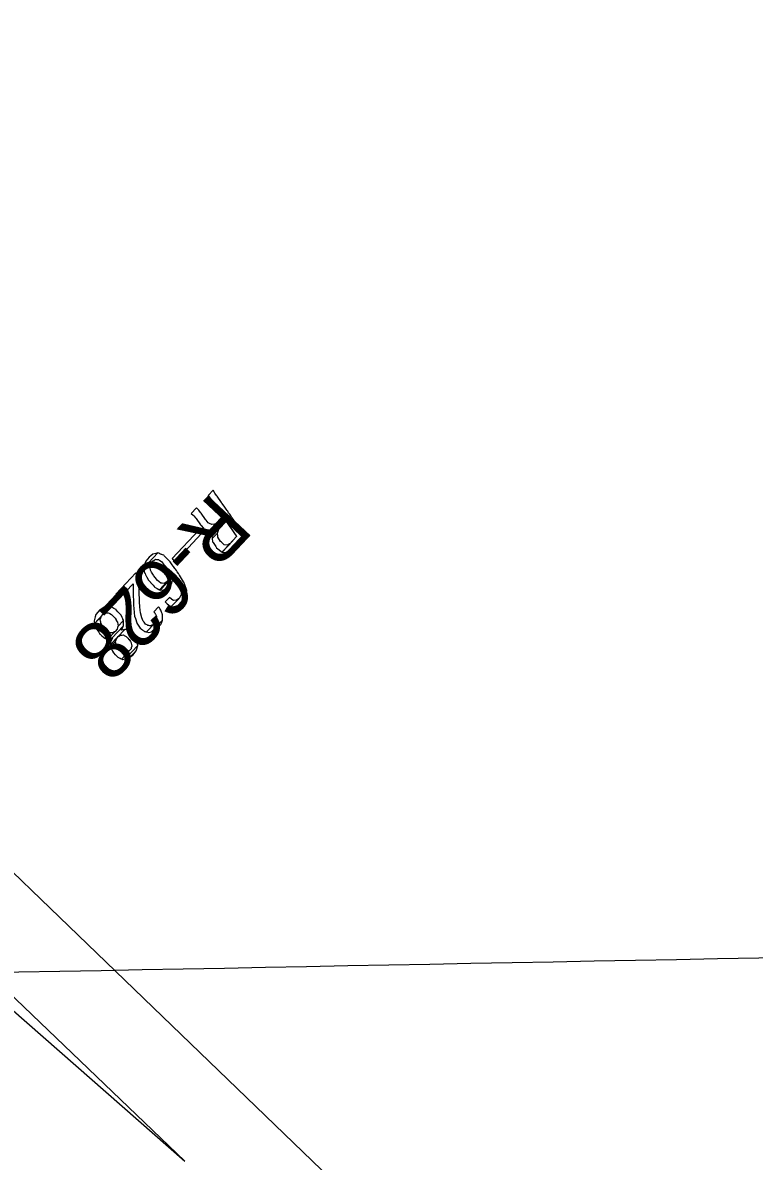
# Model space of a CAD drawing. Extents: x 3962991 to 3983549, y 181631 to 204078.
# Drawn here: x 3980223 to 3980744, y 188382 to 189193 of the extents above; entities that cross this region are included whole.
import ezdxf

# ---------------------------------------------------------------- set-up
doc = ezdxf.new("R2010")
doc.units = 0
for name, color, linetype in [('V-ANNO-MASK', 7, 'Continuous'), ('V-ANNO-MASK2', 7, 'Continuous'), ('V-GRID-MAJR', 7, 'Continuous'), ('V-RIVR-RANG-IDEN', 7, 'Continuous'), ('V-RRAP-FSHR', 7, 'Continuous'), ('V-TOPO-DPTH', 7, 'Continuous'), ('V-TOPO-MINR', 7, 'Continuous')]:
    doc.layers.add(name, color=color, linetype=linetype)

msp = doc.modelspace()

# ---------------------------------------------------------------- linework, layer by layer
at = {"layer": 'V-ANNO-MASK2'}
for points in [[(3980359.8, 188858.11), (3980358.66, 188859.76), (3980355.14, 188856.01), (3980356.29, 188854.37), (3980356.53, 188854.02), (3980357.7, 188852.34), (3980358.05, 188851.83), (3980361.14, 188847.41), (3980361.53, 188846.84), (3980362.97, 188844.78), (3980363.57, 188843.93), (3980364.51, 188842.56), (3980365.19, 188841.58), (3980365.41, 188841.28), (3980365.59, 188841.01), (3980355.97, 188830.74), (3980357.6, 188830.8), (3980360.25, 188832.18), (3980359.04, 188830.38), (3980357.87, 188827.31), (3980357.92, 188826.94), (3980367.94, 188837.63), (3980368.06, 188837.48), (3980368.67, 188836.6), (3980369.67, 188835.16), (3980370, 188834.69), (3980372.01, 188831.81), (3980372.54, 188831.04), (3980374.04, 188828.9), (3980375.14, 188827.33), (3980375.36, 188826.99), (3980375.37, 188827), (3980375.46, 188826.86), (3980375.5, 188826.79), (3980365.16, 188815.76), (3980368.78, 188815.45), (3980372.15, 188817.22), (3980375.31, 188820.34), (3980381.51, 188826.95), (3980381.41, 188827.1), (3980380.69, 188828.15), (3980379.01, 188830.54), (3980378.97, 188830.61), (3980378.87, 188830.74), (3980378.65, 188831.07), (3980377.55, 188832.64), (3980376.05, 188834.79), (3980375.52, 188835.55), (3980373.51, 188838.44), (3980373.19, 188838.91), (3980372.18, 188840.35), (3980371.57, 188841.23), (3980371.46, 188841.39), (3980371.29, 188841.63), (3980370.56, 188842.68), (3980370.36, 188842.97), (3980369.79, 188843.79), (3980369.11, 188844.76), (3980368.93, 188845.03), (3980368.71, 188845.33), (3980368.03, 188846.32), (3980367.08, 188847.67), (3980366.49, 188848.53), (3980365.04, 188850.6), (3980364.66, 188851.16), (3980361.57, 188855.59), (3980361.22, 188856.1), (3980360.04, 188857.77)], [(3980348.32, 188845.86), (3980346.99, 188847.31), (3980343.15, 188843.22), (3980344.62, 188841.91), (3980344.9, 188841.61), (3980346.23, 188840.11), (3980346.6, 188839.61), (3980349.75, 188835.25), (3980350.15, 188834.7), (3980351.81, 188832.87), (3980352.49, 188832.11), (3980353.95, 188831.29), (3980355, 188830.7), (3980355.52, 188830.72), (3980355.97, 188830.74), (3980362.27, 188837.47), (3980360.21, 188835.73), (3980359.62, 188835.63), (3980357.72, 188835.32), (3980356.25, 188836.12), (3980355.32, 188836.61), (3980353.72, 188838.51), (3980353.28, 188839.02), (3980350.19, 188843.45), (3980349.82, 188843.94), (3980348.59, 188845.55)], [(3980362.86, 188831.94), (3980365.06, 188834.56), (3980357.92, 188826.94), (3980357.95, 188826.69), (3980358.12, 188825.34), (3980361.75, 188829.23)], [(3980350.53, 188828.86), (3980348.69, 188831.49), (3980329.67, 188811.19), (3980331.51, 188808.56)], [(3980362.1, 188827.08), (3980361.75, 188829.22), (3980358.12, 188825.34), (3980358.39, 188823.12), (3980358.7, 188822.64), (3980360.62, 188819.65), (3980361.12, 188818.86), (3980363.11, 188817.23), (3980364.56, 188816.03), (3980364.85, 188815.78), (3980365.06, 188815.77), (3980370.86, 188821.95), (3980370.3, 188821.59), (3980368.96, 188820.74), (3980366.65, 188821.01), (3980364.76, 188822.74), (3980364.09, 188823.35), (3980362.21, 188826.39)], [(3980372.66, 188823.76), (3980370.86, 188821.95), (3980365.06, 188815.77), (3980365.16, 188815.76)], [(3980314.41, 188813.12), (3980313.11, 188812.05), (3980310.77, 188809.23), (3980310.56, 188808.67), (3980310.56, 188808.67), (3980309.35, 188805.51), (3980309.47, 188804.44), (3980319.44, 188815.08), (3980318, 188814.73), (3980315.72, 188814.18)], [(3980320.66, 188814.6), (3980319.44, 188815.08), (3980309.47, 188804.44), (3980309.65, 188802.84), (3980315.94, 188809.56), (3980316.42, 188809.83), (3980317.72, 188810.57), (3980318.49, 188810.55), (3980318.74, 188810.54), (3980319.72, 188810.51), (3980320.4, 188810.02), (3980320.78, 188809.74), (3980321.9, 188808.93), (3980323.48, 188807.12), (3980323.81, 188806.74), (3980324.78, 188805.61), (3980324.9, 188805.43), (3980326.3, 188803.13), (3980326.95, 188802.07), (3980327, 188801.83), (3980327.01, 188801.84), (3980327.48, 188799.88), (3980327.66, 188799.12), (3980327.33, 188797.03), (3980327.29, 188796.78), (3980325.91, 188794.66), (3980320.5, 188788.88), (3980320.88, 188788.66), (3980321.01, 188788.67), (3980329.95, 188798.21), (3980329.98, 188798.18), (3980330.8, 188796.95), (3980331.35, 188796.13), (3980331.5, 188795.91), (3980332.31, 188794.68), (3980334.5, 188791.09), (3980334.54, 188790.99), (3980334.63, 188790.79), (3980335.36, 188788.98), (3980335.87, 188787.72), (3980335.87, 188787.52), (3980335.87, 188786.74), (3980335.86, 188785.04), (3980335.53, 188784.49), (3980334.51, 188782.77), (3980329.2, 188777.1), (3980329.32, 188777.05), (3980329.32, 188777.05), (3980330.04, 188776.77), (3980333.61, 188777.58), (3980339.38, 188783.74), (3980339.86, 188787.25), (3980340.02, 188788.47), (3980339.97, 188788.6), (3980339.8, 188789.05), (3980339.75, 188789.19), (3980339.29, 188790.39), (3980339.08, 188790.94), (3980339.03, 188791.09), (3980338.54, 188792.37), (3980337.84, 188794.21), (3980337.75, 188794.42), (3980337.7, 188794.51), (3980335.47, 188798.05), (3980334.68, 188799.3), (3980334.53, 188799.53), (3980334.01, 188800.37), (3980333.21, 188801.63), (3980333.19, 188801.66), (3980333.13, 188801.73), (3980332.88, 188802.09), (3980332.61, 188802.46), (3980332.53, 188802.58), (3980331.83, 188803.56), (3980331.44, 188804.1), (3980330.44, 188805.5), (3980330.32, 188805.66), (3980329.61, 188806.65), (3980328.06, 188808.81), (3980327.92, 188808.96), (3980326.89, 188810.03), (3980326.54, 188810.39), (3980324.87, 188812.11), (3980323.92, 188813.09), (3980323.6, 188813.43), (3980322.77, 188813.76), (3980322.03, 188814.05), (3980321.84, 188814.13), (3980321.26, 188814.36), (3980320.82, 188814.53)], [(3980314.55, 188807.83), (3980315.94, 188809.56), (3980309.65, 188802.84), (3980309.67, 188802.63)], [(3980305.73, 188798.02), (3980303.68, 188800.98), (3980289.37, 188785.71), (3980291.43, 188782.76), (3980291.68, 188782.4), (3980301.79, 188793.19), (3980301.82, 188787.16), (3980301.86, 188784.13), (3980301.9, 188781.64), (3980302.07, 188777.78), (3980302.16, 188775.81), (3980302.55, 188772.57), (3980302.83, 188770.17), (3980303.35, 188768.46), (3980304.34, 188765.24), (3980304.35, 188765.19), (3980305.8, 188763), (3980306.27, 188762.29), (3980306.82, 188761.45), (3980307.39, 188761.02), (3980307.74, 188760.76), (3980308.41, 188760.27), (3980308.96, 188759.85), (3980309.34, 188759.56), (3980309.78, 188759.23), (3980310.31, 188759.11), (3980310.8, 188759), (3980311.2, 188758.91), (3980311.32, 188758.88), (3980311.39, 188758.87), (3980317.42, 188765.31), (3980316.84, 188764.78), (3980315.92, 188763.94), (3980315.14, 188763.63), (3980314.16, 188763.22), (3980313.59, 188763.29), (3980312.92, 188763.38), (3980312.33, 188763.44), (3980311.72, 188763.8), (3980311, 188764.23), (3980310.61, 188764.46), (3980310.16, 188765.01), (3980309.53, 188765.77), (3980309, 188766.42), (3980307.86, 188768.94), (3980307.84, 188768.97), (3980307.05, 188772.41), (3980306.82, 188774.43), (3980306.55, 188776.84), (3980306.36, 188780.3), (3980306.25, 188782.25), (3980306.1, 188786.13), (3980306, 188788.55), (3980305.92, 188791.53), (3980305.75, 188797.41)], [(3980314.21, 188806.83), (3980314.54, 188807.83), (3980309.67, 188802.63), (3980309.73, 188802.05), (3980309.82, 188801.3), (3980309.84, 188801.05), (3980310.22, 188800.37), (3980310.65, 188799.61), (3980310.89, 188799.18), (3980311.59, 188797.93), (3980312.81, 188795.73), (3980313.14, 188795.35), (3980314.1, 188794.21), (3980314.11, 188794.22), (3980314.24, 188794.06), (3980315.94, 188792.06), (3980316.71, 188791.15), (3980316.84, 188790.99), (3980318.34, 188790.13), (3980318.92, 188789.79), (3980319.97, 188789.18), (3980320.1, 188789.11), (3980320.5, 188788.88), (3980325.91, 188794.66), (3980324.34, 188793.64), (3980323.86, 188793.33), (3980322.39, 188793.49), (3980321.58, 188793.58), (3980320.25, 188794.62), (3980320.09, 188794.75), (3980319.14, 188795.49), (3980317.5, 188797.54), (3980317.37, 188797.69), (3980316.43, 188798.86), (3980316.17, 188799.32), (3980314.93, 188801.5), (3980314.23, 188802.75), (3980314.13, 188803.33), (3980313.95, 188804.35), (3980313.8, 188805.27), (3980313.75, 188805.5)], [(3980329.95, 188798.16), (3980329.95, 188798.21), (3980321.01, 188788.67), (3980321.06, 188788.67), (3980323.15, 188788.79), (3980324.54, 188788.86), (3980325.64, 188789.66), (3980327.32, 188790.86), (3980329.21, 188793.47), (3980329.37, 188794.02), (3980329.94, 188796.02)], [(3980339.11, 188783.36), (3980339.37, 188783.73), (3980333.61, 188777.58), (3980333.72, 188777.61), (3980336.81, 188780.12), (3980336.82, 188780.12)], [(3980278.89, 188775.09), (3980277.93, 188774.49), (3980275.25, 188771.21), (3980274.8, 188769.7), (3980273.88, 188766.64), (3980274.28, 188764.93), (3980280.17, 188771.22), (3980280.68, 188771.54), (3980280.72, 188771.57), (3980281.81, 188772.25), (3980282.68, 188772.34), (3980284.03, 188772.47), (3980284.69, 188772.14), (3980285.14, 188771.91), (3980286.34, 188771.31), (3980286.41, 188771.27), (3980287.74, 188769.83), (3980288.84, 188768.64), (3980288.87, 188768.6), (3980289.62, 188767.36), (3980289.77, 188767.1), (3980290.57, 188765.75), (3980290.79, 188764.4), (3980290.82, 188764.25), (3980291, 188763.12), (3980290.87, 188762.71), (3980294.89, 188767), (3980294.8, 188767.18), (3980294.38, 188768.05), (3980294.33, 188768.18), (3980293.83, 188769.22), (3980293.13, 188770.69), (3980292.99, 188770.96), (3980292.06, 188772.01), (3980292.02, 188772.04), (3980290.94, 188773.24), (3980289.63, 188774.71), (3980289.57, 188774.77), (3980288.4, 188775.39), (3980287.95, 188775.62), (3980287.3, 188775.96), (3980286.47, 188776.39), (3980285.95, 188776.67), (3980285.64, 188776.82), (3980285.63, 188776.83), (3980285.41, 188776.81), (3980283.29, 188776.68), (3980281.22, 188776.55)], [(3980320.44, 188775.98), (3980319.9, 188776.84), (3980316.56, 188773.28), (3980317.12, 188772.43), (3980317.51, 188771.82), (3980317.75, 188771.44), (3980318.07, 188770.58), (3980318.33, 188769.84), (3980318.51, 188769.34), (3980318.48, 188768.52), (3980318.47, 188767.82), (3980318.44, 188767.15), (3980317.75, 188765.89), (3980317.55, 188765.53), (3980317.42, 188765.31), (3980311.39, 188758.87), (3980313, 188758.5), (3980314.91, 188758.96), (3980322.72, 188767.31), (3980322.72, 188768.86), (3980322.71, 188770.95), (3980322.7, 188771.04), (3980322.67, 188771.15), (3980322.53, 188771.52), (3980322.37, 188771.98), (3980322.19, 188772.47), (3980321.98, 188773.04), (3980321.8, 188773.55), (3980321.53, 188774.27), (3980321.08, 188774.99), (3980320.84, 188775.37)], [(3980328.98, 188782.17), (3980327.72, 188783.42), (3980324.69, 188780.19), (3980325.97, 188778.95), (3980326.85, 188778.09), (3980326.94, 188777.99), (3980327.48, 188777.79), (3980328.63, 188777.32), (3980328.77, 188777.27), (3980329.2, 188777.1), (3980334.52, 188782.78), (3980332.66, 188781.42), (3980332.45, 188781.4), (3980330.68, 188781.2), (3980330.2, 188781.47), (3980330.08, 188781.54)], [(3980279.05, 188769.8), (3980280.17, 188771.22), (3980274.28, 188764.94), (3980274.32, 188764.75), (3980274.32, 188764.76), (3980274.32, 188764.74), (3980278.95, 188769.68)], [(3980278.72, 188768.95), (3980278.95, 188769.68), (3980274.32, 188764.74), (3980274.41, 188764.36), (3980274.41, 188764.36), (3980274.57, 188763.68), (3980274.81, 188762.63), (3980275, 188761.81), (3980275.29, 188761.4), (3980276.03, 188760.31), (3980276.07, 188760.25), (3980277.2, 188758.58), (3980277.21, 188758.59), (3980278.13, 188757.22), (3980278.18, 188757.19), (3980279.27, 188756.32), (3980279.49, 188756.13), (3980279.5, 188756.14), (3980280.67, 188755.19), (3980281.52, 188754.51), (3980281.61, 188754.43), (3980282.66, 188754.22), (3980282.88, 188754.17), (3980283.3, 188754.09), (3980283.82, 188753.99), (3980283.98, 188753.95), (3980288.89, 188759.19), (3980288.49, 188758.97), (3980287.19, 188758.24), (3980286.68, 188758.23), (3980286.42, 188758.23), (3980285.16, 188758.21), (3980284.98, 188758.2), (3980284.02, 188758.76), (3980282.69, 188759.54), (3980282.5, 188759.76), (3980281.58, 188760.83), (3980281.55, 188760.87), (3980280.49, 188762.09), (3980279.46, 188763.86), (3980279.42, 188763.93), (3980278.75, 188765.09), (3980278.65, 188765.7), (3980278.5, 188766.57), (3980278.3, 188767.66)], [(3980321.87, 188765.2), (3980322.72, 188767.3), (3980314.91, 188758.96), (3980316.36, 188759.32), (3980318.31, 188760.79), (3980321.44, 188764.13)], [(3980294.89, 188766.46), (3980294.89, 188766.99), (3980290.87, 188762.71), (3980290.62, 188761.9), (3980290.3, 188760.9), (3980288.89, 188759.19), (3980283.98, 188753.96), (3980284.7, 188753.81), (3980286.6, 188754.32), (3980294.87, 188763.14), (3980294.88, 188764.66), (3980294.88, 188765.59), (3980294.88, 188765.79)], [(3980294.41, 188762.21), (3980294.86, 188763.14), (3980286.6, 188754.32), (3980287.15, 188754.46), (3980285.92, 188752.12), (3980285.59, 188751.49), (3980285.61, 188749.9), (3980295.73, 188760.7), (3980293.69, 188760.14), (3980293.35, 188760.05)], [(3980295.92, 188760.65), (3980295.73, 188760.69), (3980285.61, 188749.9), (3980285.62, 188749.65), (3980291.14, 188755.55), (3980291.57, 188755.82), (3980292.74, 188756.57), (3980293.57, 188756.63), (3980294.03, 188756.66), (3980294.03, 188756.66), (3980294.84, 188756.72), (3980295.41, 188756.39), (3980295.8, 188756.15), (3980295.8, 188756.16), (3980296.9, 188755.51), (3980297.76, 188754.61), (3980298.04, 188754.31), (3980298.78, 188753.53), (3980298.84, 188753.46), (3980299.77, 188751.97), (3980300.36, 188751.01), (3980300.37, 188750.97), (3980300.63, 188749.67), (3980300.64, 188749.67), (3980300.74, 188749.14), (3980300.81, 188748.8), (3980300.44, 188747.48), (3980300.44, 188747.48), (3980300.28, 188746.93), (3980299, 188745.3), (3980293.67, 188739.61), (3980294.42, 188739.29), (3980296.04, 188739.58), (3980305, 188749.15), (3980304.82, 188750.39), (3980304.68, 188751.36), (3980304.65, 188751.59), (3980304.6, 188751.92), (3980304.49, 188752.72), (3980304.43, 188753.09), (3980304.2, 188753.47), (3980303.6, 188754.42), (3980303.58, 188754.45), (3980302.98, 188755.4), (3980302.05, 188756.88), (3980302, 188756.96), (3980301.2, 188757.69), (3980300.9, 188757.96), (3980299.99, 188758.81), (3980299.07, 188759.65), (3980298.75, 188759.95), (3980298.04, 188760.12), (3980297.42, 188760.28), (3980297.07, 188760.36), (3980296.44, 188760.52), (3980296.06, 188760.61)], [(3980319.19, 188761.46), (3980321.43, 188764.13), (3980318.31, 188760.79), (3980319.19, 188761.46)], [(3980289.89, 188754.03), (3980291.14, 188755.55), (3980285.62, 188749.65), (3980285.62, 188749.47), (3980285.63, 188748.98), (3980285.64, 188748.16), (3980289.22, 188751.98), (3980289.64, 188753.26)], [(3980289.29, 188751.6), (3980289.21, 188751.98), (3980285.64, 188748.16), (3980285.64, 188747.71), (3980285.93, 188747.2), (3980286.26, 188746.62), (3980286.49, 188746.22), (3980287.13, 188745.08), (3980287.77, 188743.94), (3980288.05, 188743.66), (3980288.81, 188742.88), (3980288.87, 188742.82), (3980290.06, 188741.6), (3980290.82, 188740.83), (3980290.84, 188740.8), (3980291.9, 188740.36), (3980292.34, 188740.17), (3980292.62, 188740.05), (3980293.24, 188739.79), (3980293.5, 188739.68), (3980293.67, 188739.61), (3980299.01, 188745.31), (3980298.33, 188744.84), (3980297.32, 188744.15), (3980296.37, 188744.06), (3980295.93, 188744.01), (3980295.26, 188743.93), (3980294.26, 188744.45), (3980294.23, 188744.47), (3980293.22, 188744.98), (3980292.08, 188746.25), (3980292.02, 188746.31), (3980291.29, 188747.12), (3980291.07, 188747.47), (3980290.38, 188748.55), (3980289.69, 188749.63), (3980289.58, 188750.17), (3980289.43, 188750.94)], [(3980304.05, 188746.05), (3980305, 188749.14), (3980296.04, 188739.58), (3980298.38, 188740.01), (3980299.71, 188741.04), (3980303.87, 188745.47)], [(3980301.47, 188742.4), (3980303.86, 188745.47), (3980299.71, 188741.04)]]:
    msp.add_lwpolyline(points, close=True, dxfattribs=at)
at = {"layer": 'V-GRID-MAJR'}
msp.add_spline([(3971886.05, 188358.46), (3973487.19, 188388.71), (3978814.65, 188489.84), (3982563.08, 188561.47)], degree=3, dxfattribs=at)
at = {"layer": 'V-RRAP-FSHR'}
msp.add_lwpolyline([(3979428.27, 189333.96), (3980015.69, 188780.87), (3980435.98, 188375.64), (3980642.57, 188188.79), (3980682.66, 188148.44)], dxfattribs=at)
at = {"layer": 'V-TOPO-DPTH'}
msp.add_lwpolyline([(3979550.21, 189095.01), (3980104.46, 188587.91), (3980115.29, 188578.06), (3980126.17, 188568.26), (3980137.1, 188558.53), (3980148.08, 188548.85), (3980338.53, 188381.93), (3979891.46, 188810.17), (3979550.21, 189095.01)], dxfattribs=at)
at = {"layer": 'V-TOPO-MINR'}
for points in [[(3979550.21, 189095.01), (3980104.46, 188587.91), (3980115.29, 188578.06), (3980126.17, 188568.26), (3980137.1, 188558.53), (3980148.08, 188548.85), (3980338.53, 188381.93)], [(3979550.21, 189095.01), (3980104.46, 188587.91), (3980115.29, 188578.06), (3980126.17, 188568.26), (3980137.1, 188558.53), (3980148.08, 188548.85), (3980338.53, 188381.93), (3979891.46, 188810.17), (3979550.21, 189095.01)]]:
    msp.add_lwpolyline(points, dxfattribs=at)

# ---------------------------------------------------------------- texts
at = {"layer": 'V-ANNO-MASK'}
msp.add_text('R-628  ', height=41.5, rotation=226.86174, dxfattribs=at).set_placement((3980358.23, 188859.3))
at = {"layer": 'V-RIVR-RANG-IDEN'}
msp.add_text('R-628  ', height=41.5, rotation=226.86174, dxfattribs=at).set_placement((3980358.23, 188859.3))

doc.saveas('drawing.dxf')
